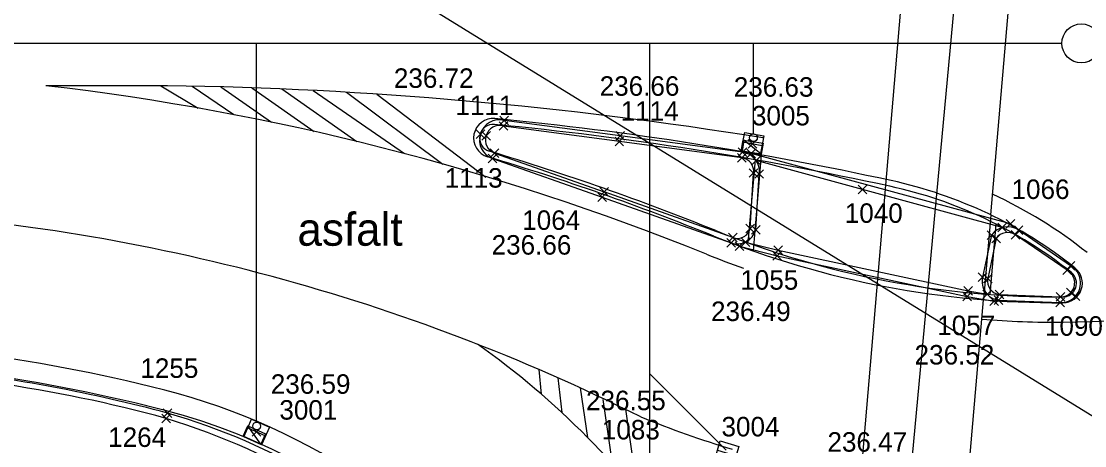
# Model space of a CAD drawing. Extents: x -264205 to -263615, y -1242401 to -1242031.
# Drawn here: x -263835.79 to -263808.5, y -1242314.46 to -1242303.58 of the extents above; entities that cross this region are included whole.
import ezdxf

# ---------------------------------------------------------------- set-up
doc = ezdxf.new("R2010")
doc.units = 0
for name, color, linetype in [('BODY_SYMBOL A CISLO_2-1', 7, 'Continuous'), ('BODY_VYSKA_2-1', 7, 'Continuous'), ('KOORDINACNA_SITUACIA_DSP', 7, 'Continuous'), ('POPIS', 7, 'Continuous'), ('PROJEKT_DRS_TDZ_VODOROVNE', 7, 'Continuous'), ('RAM_NA_TLAC_1-250_SITUACIA_2-2', 7, 'Continuous'), ('SO_20-1_OBRUBNIKY_DOLNA_HRANA', 7, 'Continuous'), ('SO_20-1_OBRUBNIKY_HORNA_HRANA', 7, 'Continuous'), ('SO_20-1_UV', 7, 'Continuous')]:
    doc.layers.add(name, color=color, linetype=linetype)

msp = doc.modelspace()

# ---------------------------------------------------------------- linework, layer by layer
at = {"layer": 'BODY_SYMBOL A CISLO_2-1'}
for p, q in [((-263823.53, -1242306.376), (-263823.309, -1242306.154)), ((-263823.309, -1242306.376), (-263823.53, -1242306.154)), ((-263823.511, -1242306.231), (-263823.29, -1242306.009)), ((-263823.29, -1242306.231), (-263823.511, -1242306.009)), ((-263824.118, -1242306.589), (-263823.897, -1242306.367)), ((-263823.897, -1242306.589), (-263824.118, -1242306.367)), ((-263823.973, -1242306.629), (-263823.752, -1242306.407)), ((-263823.752, -1242306.629), (-263823.973, -1242306.407)), ((-263820.535, -1242306.632), (-263820.314, -1242306.41)), ((-263820.314, -1242306.632), (-263820.535, -1242306.41)), ((-263820.557, -1242306.775), (-263820.335, -1242306.555)), ((-263820.335, -1242306.775), (-263820.557, -1242306.555)), ((-263817.141, -1242306.83), (-263816.92, -1242306.61)), ((-263816.92, -1242306.83), (-263817.141, -1242306.61)), ((-263823.813, -1242307.207), (-263823.592, -1242306.985)), ((-263823.592, -1242307.207), (-263823.813, -1242306.985)), ((-263823.761, -1242307.072), (-263823.54, -1242306.85)), ((-263823.54, -1242307.072), (-263823.761, -1242306.85)), ((-263817.414, -1242307.194), (-263817.193, -1242306.974)), ((-263817.193, -1242307.194), (-263817.414, -1242306.974)), ((-263817.399, -1242307.048), (-263817.177, -1242306.826)), ((-263817.177, -1242307.048), (-263817.399, -1242306.826)), ((-263817.174, -1242307.078), (-263816.953, -1242306.856)), ((-263816.953, -1242307.078), (-263817.174, -1242306.856)), ((-263817.047, -1242307.262), (-263816.826, -1242307.041)), ((-263816.826, -1242307.262), (-263817.047, -1242307.041)), ((-263817.111, -1242307.58), (-263816.889, -1242307.36)), ((-263816.889, -1242307.58), (-263817.111, -1242307.36)), ((-263816.967, -1242307.606), (-263816.746, -1242307.386)), ((-263816.746, -1242307.606), (-263816.967, -1242307.386)), ((-263814.317, -1242308.005), (-263814.095, -1242307.785)), ((-263814.095, -1242308.005), (-263814.317, -1242307.785)), ((-263820.995, -1242308.201), (-263820.774, -1242307.98)), ((-263820.774, -1242308.201), (-263820.995, -1242307.98)), ((-263820.947, -1242308.065), (-263820.726, -1242307.843)), ((-263820.726, -1242308.065), (-263820.947, -1242307.843)), ((-263817.198, -1242309.002), (-263816.977, -1242308.782)), ((-263816.977, -1242309.002), (-263817.198, -1242308.782)), ((-263817.057, -1242309.041), (-263816.835, -1242308.819)), ((-263816.835, -1242309.041), (-263817.057, -1242308.819)), ((-263810.731, -1242308.977), (-263810.509, -1242308.755)), ((-263810.509, -1242308.977), (-263810.731, -1242308.755)), ((-263810.517, -1242308.884), (-263810.296, -1242308.664)), ((-263810.296, -1242308.884), (-263810.517, -1242308.664)), ((-263810.307, -1242309.046), (-263810.087, -1242308.826)), ((-263810.087, -1242309.046), (-263810.307, -1242308.826)), ((-263817.69, -1242309.372), (-263817.469, -1242309.15)), ((-263817.469, -1242309.372), (-263817.69, -1242309.15)), ((-263817.642, -1242309.238), (-263817.421, -1242309.016)), ((-263817.421, -1242309.238), (-263817.642, -1242309.016)), ((-263817.323, -1242309.35), (-263817.101, -1242309.129)), ((-263817.101, -1242309.35), (-263817.323, -1242309.129)), ((-263811.008, -1242309.174), (-263810.786, -1242308.953)), ((-263810.786, -1242309.174), (-263811.008, -1242308.953)), ((-263810.886, -1242309.257), (-263810.665, -1242309.035)), ((-263810.665, -1242309.257), (-263810.886, -1242309.035)), ((-263810.393, -1242309.167), (-263810.171, -1242308.947)), ((-263810.171, -1242309.167), (-263810.393, -1242308.947)), ((-263817.476, -1242309.46), (-263817.254, -1242309.238)), ((-263817.254, -1242309.46), (-263817.476, -1242309.238)), ((-263816.479, -1242309.558), (-263816.258, -1242309.336)), ((-263816.258, -1242309.558), (-263816.479, -1242309.336)), ((-263816.506, -1242309.7), (-263816.285, -1242309.478)), ((-263816.285, -1242309.7), (-263816.506, -1242309.478)), ((-263809.061, -1242310.075), (-263808.84, -1242309.853)), ((-263808.84, -1242310.075), (-263809.061, -1242309.853)), ((-263808.976, -1242309.957), (-263808.755, -1242309.735)), ((-263808.755, -1242309.957), (-263808.976, -1242309.735)), ((-263811.237, -1242310.252), (-263811.016, -1242310.032)), ((-263811.016, -1242310.252), (-263811.237, -1242310.032)), ((-263811.098, -1242310.288), (-263810.877, -1242310.066)), ((-263810.877, -1242310.288), (-263811.098, -1242310.066)), ((-263811.633, -1242310.745), (-263811.412, -1242310.524)), ((-263811.412, -1242310.745), (-263811.633, -1242310.524)), ((-263811.604, -1242310.603), (-263811.383, -1242310.382)), ((-263811.383, -1242310.603), (-263811.604, -1242310.382)), ((-263811.114, -1242310.691), (-263810.893, -1242310.47)), ((-263810.893, -1242310.691), (-263811.114, -1242310.47)), ((-263810.802, -1242310.694), (-263810.58, -1242310.472)), ((-263810.58, -1242310.694), (-263810.802, -1242310.472)), ((-263809.236, -1242310.754), (-263809.014, -1242310.532)), ((-263809.014, -1242310.754), (-263809.236, -1242310.532)), ((-263808.969, -1242310.644), (-263808.747, -1242310.423)), ((-263808.747, -1242310.644), (-263808.969, -1242310.423)), ((-263808.849, -1242310.737), (-263808.628, -1242310.515)), ((-263808.628, -1242310.737), (-263808.849, -1242310.515)), ((-263810.94, -1242310.869), (-263810.719, -1242310.647)), ((-263810.719, -1242310.869), (-263810.94, -1242310.647)), ((-263810.823, -1242310.842), (-263810.602, -1242310.62)), ((-263810.602, -1242310.842), (-263810.823, -1242310.62)), ((-263809.24, -1242310.9), (-263809.019, -1242310.678)), ((-263809.019, -1242310.9), (-263809.24, -1242310.678)), ((-263832.149, -1242313.735), (-263831.927, -1242313.514)), ((-263831.927, -1242313.735), (-263832.149, -1242313.514)), ((-263832.185, -1242313.873), (-263831.964, -1242313.651)), ((-263831.964, -1242313.873), (-263832.185, -1242313.651)), ((-263829.867, -1242314.218), (-263829.645, -1242313.997)), ((-263829.645, -1242314.218), (-263829.867, -1242313.997))]:
    msp.add_line(p, q, dxfattribs=at)
at = {"layer": 'KOORDINACNA_SITUACIA_DSP'}
for p, q in [((-263809.091, -1242304.153), (-263853.415, -1242304.148)), ((-263829.755, -1242313.856), (-263829.755, -1242304.151)), ((-263819.667, -1242332.824), (-263819.667, -1242304.147)), ((-263817.005, -1242306.465), (-263817.005, -1242304.152)), ((-263817.296, -1242306.914), (-263817.252, -1242306.627)), ((-263817.252, -1242306.627), (-263817.296, -1242306.914)), ((-263817.252, -1242306.627), (-263816.757, -1242306.703)), ((-263816.802, -1242306.99), (-263817.252, -1242306.627)), ((-263816.802, -1242306.99), (-263817.252, -1242306.627)), ((-263816.757, -1242306.703), (-263816.802, -1242306.99)), ((-263816.802, -1242306.99), (-263817.296, -1242306.914)), ((-263817.296, -1242306.914), (-263816.802, -1242306.99)), ((-263816.964, -1242307.132), (-263817.145, -1242309.262)), ((-263816.803, -1242307.008), (-263817.012, -1242309.468)), ((-263810.912, -1242308.547), (-263811.097, -1242310.721)), ((-263810.781, -1242308.779), (-263810.935, -1242310.583)), ((-263817.708, -1242314.574), (-263819.667, -1242312.615)), ((-263830.101, -1242314.219), (-263829.983, -1242313.954)), ((-263829.983, -1242313.954), (-263830.101, -1242314.219)), ((-263829.983, -1242313.954), (-263829.527, -1242314.158)), ((-263829.645, -1242314.423), (-263829.983, -1242313.954)), ((-263829.645, -1242314.423), (-263829.983, -1242313.954)), ((-263829.645, -1242314.423), (-263830.101, -1242314.219)), ((-263830.101, -1242314.219), (-263829.645, -1242314.423)), ((-263829.527, -1242314.158), (-263829.645, -1242314.423))]:
    msp.add_line(p, q, dxfattribs=at)
for centre, radius in [((-263808.591, -1242304.147), 0.5), ((-263817.005, -1242306.565), 0.1), ((-263829.755, -1242313.956), 0.1)]:
    msp.add_circle(centre, radius, dxfattribs=at)
for centre, radius, start, end in [((-263823.686, -1242306.574), 0.5, 84.5031, 253.3726), ((-263832, -1242392.966), 87.291, 77.74517, 84.50312), ((-263823.686, -1242306.574), 0.35, 84.5031, 253.3726), ((-263832, -1242392.966), 87.141, 77.74517, 84.50312), ((-263842.678, -1242370.168), 66.019, 68.01969, 73.37264), ((-263842.678, -1242370.168), 65.869, 68.01969, 73.37264), ((-263815.913, -1242318.902), 11.5, 51.4912, 77.7452), ((-263815.913, -1242318.902), 11.35, 51.4912, 77.7452), ((-263809.228, -1242287.295), 23.5, 248.0197, 270.4085), ((-263809.228, -1242287.295), 23.35, 248.0197, 270.4085), ((-263809.064, -1242310.295), 0.5, 270.4085, 51.4912), ((-263809.064, -1242310.295), 0.35, 270.4085, 51.4912), ((-263842.427, -1242353.351), 41.111, 76.1362, 90.2415), ((-263836.184, -1242329.025), 16, 326.2529, 76.9695)]:
    msp.add_arc(centre, radius, start, end, dxfattribs=at)
at = {"layer": 'PROJEKT_DRS_TDZ_VODOROVNE'}
for p, q in [((-263810.915, -1242308.545), (-263810.255, -1242300.841)), ((-263832.039, -1242305.232), (-263835.165, -1242305.232)), ((-263832.216, -1242305.232), (-263831.251, -1242305.806)), ((-263831.408, -1242305.243), (-263830.341, -1242305.974)), ((-263830.671, -1242305.261), (-263829.376, -1242306.167)), ((-263829.878, -1242305.286), (-263828.277, -1242306.405)), ((-263829.11, -1242305.316), (-263827.186, -1242306.661)), ((-263828.303, -1242305.354), (-263825.963, -1242306.972)), ((-263827.448, -1242305.4), (-263824.977, -1242307.241)), ((-263826.672, -1242305.448), (-263823.87, -1242307.573)), ((-263811.571, -1242316.2), (-263811.101, -1242310.72)), ((-263822.515, -1242312.506), (-263822.452, -1242313.137)), ((-263822.025, -1242312.72), (-263821.925, -1242313.608)), ((-263821.448, -1242312.98), (-263821.265, -1242314.247)), ((-263820.866, -1242313.273), (-263820.628, -1242314.918)), ((-263820.29, -1242313.528), (-263819.981, -1242315.667))]:
    msp.add_line(p, q, dxfattribs=at)
for points in [[(-263831.211, -1242326.873), (-263816.19, -1242319.41), (-263814.291, -1242315.804), (-263813.06, -1242301.353), (-263812.968, -1242299.181), (-263802.618, -1242291.831), (-263801.478, -1242290.893), (-263800.257, -1242289.755), (-263799.049, -1242288.464), (-263798.027, -1242287.218), (-263749.798, -1242216.488), (-263742.736, -1242211.145)], [(-263830.6, -1242328.105), (-263815.26, -1242320.378), (-263813.062, -1242316.188), (-263811.682, -1242301.389), (-263811.608, -1242300.055), (-263801.705, -1242293.023), (-263800.489, -1242292.021), (-263799.197, -1242290.817), (-263797.92, -1242289.454), (-263796.825, -1242288.118), (-263748.697, -1242217.536), (-263741.831, -1242212.341)]]:
    msp.add_lwpolyline(points, dxfattribs=at)
for centre, radius, start, end in [((-263809.228, -1242287.295), 24, 270.4085, 326.3969), ((-263842.678, -1242370.168), 65.369, 68.01969, 83.40081), ((-263833.602, -1242410.935), 105.714, 80.83552, 89.15278), ((-263815.913, -1242318.902), 12, 51.4912, 65.1468), ((-263842.518, -1242358.966), 50.583, 63.4329, 86.4022), ((-263809.228, -1242287.295), 24, 248.0197, 250.4574), ((-263809.228, -1242287.295), 24, 265.4211, 270.4085), ((-263842.485, -1242353.555), 41.823, 76.1362, 90.2415), ((-263836.184, -1242329.025), 21, 34.6339, 54.8237), ((-263836.225, -1242329.073), 16.555, 36.9462, 76.8694), ((-263809.228, -1242287.295), 28.5, 248.0197, 253.0257)]:
    msp.add_arc(centre, radius, start, end, dxfattribs=at)
at = {"layer": 'RAM_NA_TLAC_1-250_SITUACIA_2-2'}
msp.add_lwpolyline([(-263834.004, -1242297.889), (-263756.71, -1242172.264), (-263693.471, -1242211.173), (-263770.766, -1242336.799)], close=True, dxfattribs=at)
at = {"layer": 'SO_20-1_OBRUBNIKY_DOLNA_HRANA'}
for p, q in [((-263817.063, -1242306.967), (-263817.288, -1242306.937)), ((-263810.406, -1242308.774), (-263817.063, -1242306.967)), ((-263820.884, -1242308.09), (-263817.579, -1242309.261)), ((-263810.406, -1242308.774), (-263810.197, -1242308.936)), ((-263817.365, -1242309.349), (-263817.579, -1242309.261)), ((-263810.829, -1242310.758), (-263810.713, -1242310.731))]:
    msp.add_line(p, q, dxfattribs=at)
for points in [[(-263817.288, -1242306.937), (-263820.425, -1242306.521), (-263823.4, -1242306.12)], [(-263823.703, -1242307.096), (-263820.884, -1242308.09)], [(-263816.946, -1242308.93), (-263816.856, -1242307.496)], [(-263810.897, -1242309.063), (-263811.127, -1242310.142)], [(-263808.866, -1242309.846), (-263810.197, -1242308.936)], [(-263817.365, -1242309.349), (-263816.395, -1242309.589), (-263811.523, -1242310.634), (-263810.829, -1242310.758)], [(-263810.713, -1242310.731), (-263809.129, -1242310.789)]]:
    msp.add_lwpolyline(points, dxfattribs=at)
for centre, major_axis, ratio, start_param, end_param in [((-263823.524, -1242306.605), (0.185, 0.465), 0.999783, 0.129335, 1.693518), ((-263823.537, -1242306.629), (-0.201, -0.453), 0.999743, 4.819194, 6.358079), ((-263817.347, -1242307.429), (-0.223, 0.443), 0.999317, 4.112578, 5.697553), ((-263810.483, -1242309.349), (-0.502, 0.041), 0.998209, 4.188918, 5.758624), ((-263817.423, -1242308.788), (0.483, 0.121), 0.999839, 4.148248, 5.748493), ((-263809.118, -1242310.288), (0.193, 0.471), 0.999988, 4.374498, 6.15423), ((-263810.643, -1242310.242), (0.359, -0.34), 0.999903, 3.695611, 5.327884), ((-263809.106, -1242310.293), (-0.189, -0.46), 0.999728, 0.34373, 1.224576), ((-263842.443, -1242352.313), (-40.262, 2.734), 0.992518, 4.518911, 4.667632), ((-263836.917, -1242330.389), (-12.568, 12.147), 0.998664, 4.713467, 5.197044)]:
    msp.add_ellipse(centre, major_axis=major_axis, ratio=ratio, start_param=start_param, end_param=end_param, dxfattribs=at)
at = {"layer": 'SO_20-1_OBRUBNIKY_HORNA_HRANA'}
msp.add_line((-263817.531, -1242309.127), (-263820.836, -1242307.954), dxfattribs=at)
for points in [[(-263817.303, -1242307.084), (-263820.446, -1242306.665), (-263823.42, -1242306.265)], [(-263823.65, -1242306.961), (-263820.836, -1242307.954)], [(-263810.62, -1242308.866), (-263814.206, -1242307.895), (-263816.937, -1242307.151)], [(-263817.088, -1242308.892), (-263817, -1242307.47)], [(-263810.775, -1242309.146), (-263810.987, -1242310.177)], [(-263808.95, -1242309.964), (-263810.282, -1242309.057)], [(-263817.212, -1242309.239), (-263816.368, -1242309.447), (-263811.493, -1242310.492), (-263811.003, -1242310.58)], [(-263810.691, -1242310.583), (-263809.125, -1242310.643)]]:
    msp.add_lwpolyline(points, dxfattribs=at)
for centre, major_axis, ratio, start_param, end_param in [((-263823.519, -1242306.604), (0.235, 0.264), 0.999068, 0.442251, 2.051271), ((-263823.525, -1242306.629), (-0.123, -0.333), 0.999597, 4.748011, 6.276343), ((-263817.341, -1242307.426), (-0.027, 0.343), 0.999831, 4.506293, 6.094133), ((-263817.42, -1242308.802), (-0.293, -0.18), 0.999477, 0.692286, 2.325931), ((-263810.484, -1242309.349), (-0.307, 0.179), 0.999697, 4.635173, 6.202132), ((-263809.124, -1242310.284), (-0.341, 0.127), 0.999992, 2.744279, 4.570945), ((-263810.652, -1242310.243), (0.136, -0.314), 0.999837, 4.109578, 5.759605), ((-263809.115, -1242310.288), (-0.172, -0.311), 0.99925, 0.476223, 1.31312), ((-263841.309, -1242347.152), (-34.744, 1.786), 0.995607, 4.494833, 4.62376), ((-263837.329, -1242331.009), (-13.346, 12.171), 0.997839, 4.663107, 5.155176)]:
    msp.add_ellipse(centre, major_axis=major_axis, ratio=ratio, start_param=start_param, end_param=end_param, dxfattribs=at)
at = {"layer": 'SO_20-1_UV'}
for p, q in [((-263817.03, -1242306.72), (-263817.03, -1242306.72)), ((-263829.756, -1242314.107), (-263829.756, -1242314.107))]:
    msp.add_line(p, q, dxfattribs=at)
for points in [[(-263817.276, -1242306.674), (-263817.229, -1242306.428), (-263816.738, -1242306.521), (-263816.831, -1242307.012), (-263817.322, -1242306.919), (-263817.276, -1242306.674), (-263816.784, -1242306.766)], [(-263829.984, -1242314.005), (-263829.882, -1242313.777), (-263829.426, -1242313.981), (-263829.63, -1242314.437), (-263830.086, -1242314.233), (-263829.984, -1242314.005), (-263829.528, -1242314.209)], [(-263817.927, -1242314.574), (-263817.855, -1242314.335), (-263817.377, -1242314.479), (-263817.521, -1242314.957), (-263817.999, -1242314.813), (-263817.927, -1242314.574), (-263817.449, -1242314.718)]]:
    msp.add_lwpolyline(points, dxfattribs=at)

# ---------------------------------------------------------------- texts
at = {"layer": 'BODY_SYMBOL A CISLO_2-1'}
for s, p in [('1111', (-263824.651, -1242305.987)), ('1114', (-263820.412, -1242306.132)), ('3005', (-263817.043, -1242306.25)), ('1113', (-263824.928, -1242307.845)), ('1066', (-263810.38, -1242308.136)), ('1040', (-263814.66, -1242308.748)), ('1064', (-263822.938, -1242308.928)), ('1055', (-263817.341, -1242310.461)), ('1057', (-263812.287, -1242311.626)), ('1090', (-263809.524, -1242311.642)), ('1255', (-263832.737, -1242312.722)), ('3001', (-263829.17, -1242313.792)), ('1083', (-263820.895, -1242314.3)), ('3004', (-263817.824, -1242314.222)), ('1264', (-263833.564, -1242314.492))]:
    msp.add_text(s, height=0.5, dxfattribs=at).set_placement(p)
at = {"layer": 'BODY_VYSKA_2-1'}
for s, p in [('236.72', (-263826.232, -1242305.288)), ('236.66', (-263820.95, -1242305.49)), ('236.63', (-263817.509, -1242305.514)), ('236.66', (-263823.723, -1242309.562)), ('236.49', (-263818.093, -1242311.265)), ('236.52', (-263812.869, -1242312.379)), ('236.59', (-263829.391, -1242313.13)), ('236.55', (-263821.3, -1242313.55)), ('236.47', (-263815.105, -1242314.614))]:
    msp.add_text(s, height=0.5, dxfattribs=at).set_placement(p)
at = {"layer": 'POPIS'}
msp.add_text('asfalt', height=0.8438, dxfattribs=at).set_placement((-263828.706, -1242309.334))

doc.saveas('drawing.dxf')
